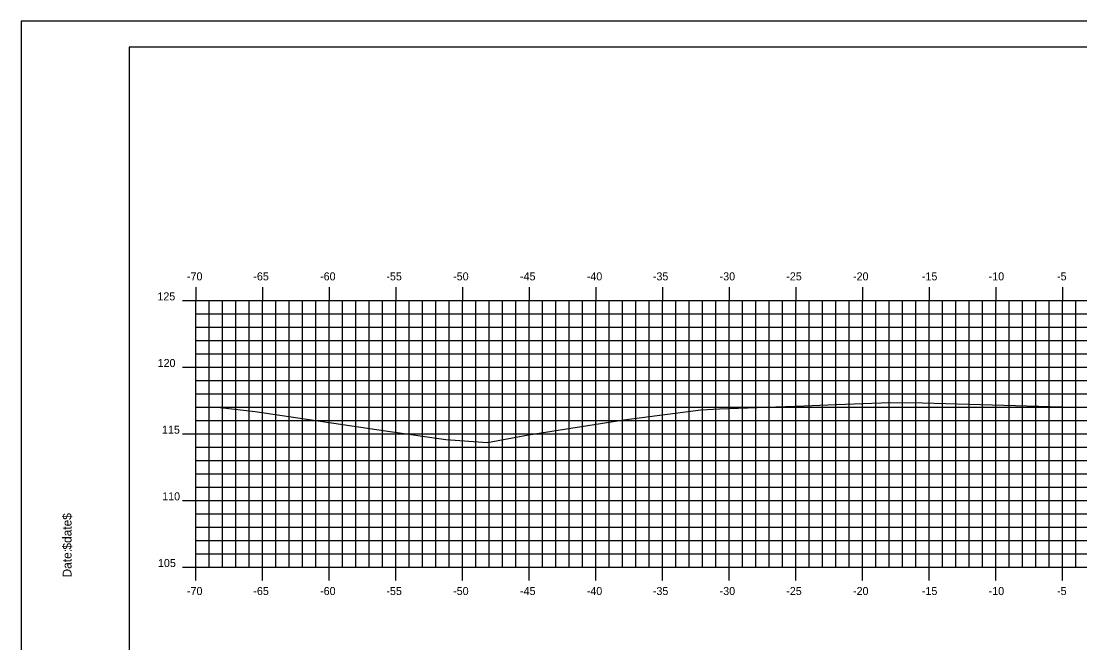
# Model space of a CAD drawing. Extents: x 853734 to 853906, y 365624 to 365734.
# Drawn here: x 853734.2 to 853813.6, y 365687.3 to 365734 of the extents above; entities that cross this region are included whole.
import ezdxf

# ---------------------------------------------------------------- set-up
doc = ezdxf.new("R2010")
doc.units = 0
for name, color, linetype in [('BORDER', 7, 'Continuous'), ('H_V ANNOTATION', 7, 'Continuous'), ('M_Roadway_Centerline', 7, 'Continuous'), ('MAJOR', 7, 'Continuous'), ('MINOR', 7, 'Continuous'), ('PLOT BOUNDARY', 7, 'Continuous'), ('S_Roadway_Centerline', 7, 'Continuous')]:
    doc.layers.add(name, color=color, linetype=linetype)

msp = doc.modelspace()

# ---------------------------------------------------------------- linework, layer by layer
at = {"layer": 'BORDER'}
msp.add_lwpolyline([(853742.331, 365627.027), (853902.331, 365627.027), (853902.331, 365732.027), (853742.331, 365732.027)], close=True, dxfattribs=at)
at = {"layer": 'MAJOR'}
for p, q in [((853747.331, 365714.029), (853747.331, 365713.027)), ((853752.331, 365714.029), (853752.331, 365713.027)), ((853757.331, 365714.029), (853757.331, 365713.027)), ((853762.331, 365714.029), (853762.331, 365713.027)), ((853767.331, 365714.029), (853767.331, 365713.027)), ((853772.331, 365714.029), (853772.331, 365713.027)), ((853777.331, 365714.029), (853777.331, 365713.027)), ((853782.331, 365714.029), (853782.331, 365713.027)), ((853787.331, 365714.029), (853787.331, 365713.027)), ((853792.331, 365714.029), (853792.331, 365713.027)), ((853797.331, 365714.029), (853797.331, 365713.027)), ((853802.331, 365714.029), (853802.331, 365713.027)), ((853807.331, 365714.029), (853807.331, 365713.027)), ((853812.331, 365714.029), (853812.331, 365713.027)), ((853746.329, 365713.027), (853747.331, 365713.027)), ((853747.331, 365713.027), (853887.331, 365713.027)), ((853747.331, 365693.027), (853747.331, 365713.027)), ((853747.331, 365693.027), (853747.331, 365713.027)), ((853747.331, 365713.027), (853887.331, 365713.027)), ((853752.331, 365693.027), (853752.331, 365713.027)), ((853757.331, 365693.027), (853757.331, 365713.027)), ((853762.331, 365693.027), (853762.331, 365713.027)), ((853767.331, 365693.027), (853767.331, 365713.027)), ((853772.331, 365693.027), (853772.331, 365713.027)), ((853777.331, 365693.027), (853777.331, 365713.027)), ((853782.331, 365693.027), (853782.331, 365713.027)), ((853787.331, 365693.027), (853787.331, 365713.027)), ((853792.331, 365693.027), (853792.331, 365713.027)), ((853797.331, 365693.027), (853797.331, 365713.027)), ((853802.331, 365693.027), (853802.331, 365713.027)), ((853807.331, 365693.027), (853807.331, 365713.027)), ((853812.331, 365693.027), (853812.331, 365713.027)), ((853746.329, 365708.027), (853747.331, 365708.027)), ((853747.331, 365708.027), (853887.331, 365708.027)), ((853746.329, 365703.027), (853747.331, 365703.027)), ((853747.331, 365703.027), (853887.331, 365703.027)), ((853746.329, 365698.027), (853747.331, 365698.027)), ((853747.331, 365698.027), (853887.331, 365698.027)), ((853746.329, 365693.027), (853747.331, 365693.027)), ((853747.331, 365693.027), (853887.331, 365693.027)), ((853747.331, 365693.027), (853887.331, 365693.027)), ((853747.331, 365692.025), (853747.331, 365693.027)), ((853752.331, 365692.025), (853752.331, 365693.027)), ((853757.331, 365692.025), (853757.331, 365693.027)), ((853762.331, 365692.025), (853762.331, 365693.027)), ((853767.331, 365692.025), (853767.331, 365693.027)), ((853772.331, 365692.025), (853772.331, 365693.027)), ((853777.331, 365692.025), (853777.331, 365693.027)), ((853782.331, 365692.025), (853782.331, 365693.027)), ((853787.331, 365692.025), (853787.331, 365693.027)), ((853792.331, 365692.025), (853792.331, 365693.027)), ((853797.331, 365692.025), (853797.331, 365693.027)), ((853802.331, 365692.025), (853802.331, 365693.027)), ((853807.331, 365692.025), (853807.331, 365693.027)), ((853812.331, 365692.025), (853812.331, 365693.027))]:
    msp.add_line(p, q, dxfattribs=at)
at = {"layer": 'MINOR'}
for p, q in [((853748.331, 365693.027), (853748.331, 365713.027)), ((853749.331, 365693.027), (853749.331, 365713.027)), ((853750.331, 365693.027), (853750.331, 365713.027)), ((853751.331, 365693.027), (853751.331, 365713.027)), ((853753.331, 365693.027), (853753.331, 365713.027)), ((853754.331, 365693.027), (853754.331, 365713.027)), ((853755.331, 365693.027), (853755.331, 365713.027)), ((853756.331, 365693.027), (853756.331, 365713.027)), ((853758.331, 365693.027), (853758.331, 365713.027)), ((853759.331, 365693.027), (853759.331, 365713.027)), ((853760.331, 365693.027), (853760.331, 365713.027)), ((853761.331, 365693.027), (853761.331, 365713.027)), ((853763.331, 365693.027), (853763.331, 365713.027)), ((853764.331, 365693.027), (853764.331, 365713.027)), ((853765.331, 365693.027), (853765.331, 365713.027)), ((853766.331, 365693.027), (853766.331, 365713.027)), ((853768.331, 365693.027), (853768.331, 365713.027)), ((853769.331, 365693.027), (853769.331, 365713.027)), ((853770.331, 365693.027), (853770.331, 365713.027)), ((853771.331, 365693.027), (853771.331, 365713.027)), ((853773.331, 365693.027), (853773.331, 365713.027)), ((853774.331, 365693.027), (853774.331, 365713.027)), ((853775.331, 365693.027), (853775.331, 365713.027)), ((853776.331, 365693.027), (853776.331, 365713.027)), ((853778.331, 365693.027), (853778.331, 365713.027)), ((853779.331, 365693.027), (853779.331, 365713.027)), ((853780.331, 365693.027), (853780.331, 365713.027)), ((853781.331, 365693.027), (853781.331, 365713.027)), ((853783.331, 365693.027), (853783.331, 365713.027)), ((853784.331, 365693.027), (853784.331, 365713.027)), ((853785.331, 365693.027), (853785.331, 365713.027)), ((853786.331, 365693.027), (853786.331, 365713.027)), ((853788.331, 365693.027), (853788.331, 365713.027)), ((853789.331, 365693.027), (853789.331, 365713.027)), ((853790.331, 365693.027), (853790.331, 365713.027)), ((853791.331, 365693.027), (853791.331, 365713.027)), ((853793.331, 365693.027), (853793.331, 365713.027)), ((853794.331, 365693.027), (853794.331, 365713.027)), ((853795.331, 365693.027), (853795.331, 365713.027)), ((853796.331, 365693.027), (853796.331, 365713.027)), ((853798.331, 365693.027), (853798.331, 365713.027)), ((853799.331, 365693.027), (853799.331, 365713.027)), ((853800.331, 365693.027), (853800.331, 365713.027)), ((853801.331, 365693.027), (853801.331, 365713.027)), ((853803.331, 365693.027), (853803.331, 365713.027)), ((853804.331, 365693.027), (853804.331, 365713.027)), ((853805.331, 365693.027), (853805.331, 365713.027)), ((853806.331, 365693.027), (853806.331, 365713.027)), ((853808.331, 365693.027), (853808.331, 365713.027)), ((853809.331, 365693.027), (853809.331, 365713.027)), ((853810.331, 365693.027), (853810.331, 365713.027)), ((853811.331, 365693.027), (853811.331, 365713.027)), ((853813.331, 365693.027), (853813.331, 365713.027)), ((853747.331, 365712.027), (853887.331, 365712.027)), ((853747.331, 365712.027), (853748.333, 365712.027)), ((853747.331, 365711.027), (853887.331, 365711.027)), ((853747.331, 365711.027), (853748.333, 365711.027)), ((853747.331, 365710.027), (853887.331, 365710.027)), ((853747.331, 365710.027), (853748.333, 365710.027)), ((853747.331, 365709.027), (853887.331, 365709.027)), ((853747.331, 365709.027), (853748.333, 365709.027)), ((853747.331, 365707.027), (853887.331, 365707.027)), ((853747.331, 365707.027), (853748.333, 365707.027)), ((853747.331, 365706.027), (853887.331, 365706.027)), ((853747.331, 365706.027), (853748.333, 365706.027)), ((853747.331, 365705.027), (853887.331, 365705.027)), ((853747.331, 365705.027), (853748.333, 365705.027)), ((853747.331, 365704.027), (853887.331, 365704.027)), ((853747.331, 365704.027), (853748.333, 365704.027)), ((853747.331, 365702.027), (853887.331, 365702.027)), ((853747.331, 365702.027), (853748.333, 365702.027)), ((853747.331, 365701.027), (853887.331, 365701.027)), ((853747.331, 365701.027), (853748.333, 365701.027)), ((853747.331, 365700.027), (853887.331, 365700.027)), ((853747.331, 365700.027), (853748.333, 365700.027)), ((853747.331, 365699.027), (853887.331, 365699.027)), ((853747.331, 365699.027), (853748.333, 365699.027)), ((853747.331, 365697.027), (853887.331, 365697.027)), ((853747.331, 365697.027), (853748.333, 365697.027)), ((853747.331, 365696.027), (853887.331, 365696.027)), ((853747.331, 365696.027), (853748.333, 365696.027)), ((853747.331, 365695.027), (853887.331, 365695.027)), ((853747.331, 365695.027), (853748.333, 365695.027)), ((853747.331, 365694.027), (853887.331, 365694.027)), ((853747.331, 365694.027), (853748.333, 365694.027))]:
    msp.add_line(p, q, dxfattribs=at)
at = {"layer": 'PLOT BOUNDARY'}
msp.add_lwpolyline([(853734.238, 365623.968), (853904.238, 365623.968), (853904.238, 365733.968), (853734.238, 365733.968)], close=True, dxfattribs=at)
at = {"layer": 'S_Roadway_Centerline'}
msp.add_lwpolyline([(853747.331, 365705.041), (853749.151, 365704.997), (853751.776, 365704.687), (853761.571, 365703.248), (853766.078, 365702.598), (853769.212, 365702.355), (853772.273, 365702.953), (853779.437, 365704.064), (853785.216, 365704.826), (853786.597, 365704.903), (853792.948, 365705.121), (853794.723, 365705.19), (853798.035, 365705.318), (853799.439, 365705.364), (853801.833, 365705.334), (853812.276, 365705.044), (853815.177, 365704.969)], dxfattribs=at)

# ---------------------------------------------------------------- texts
at = {"layer": 'BORDER'}
for s, p in [('$date$', (853738.016, 365694.332)), ('Date:', (853738.016, 365692.244))]:
    msp.add_text(s, height=0.6696, rotation=90, dxfattribs=at).set_placement(p)
at = {"layer": 'H_V ANNOTATION'}
for s, p in [('-70', (853746.673, 365714.527)), ('-65', (853751.649, 365714.527)), ('-60', (853756.657, 365714.527)), ('-55', (853761.627, 365714.527)), ('-50', (853766.635, 365714.527)), ('-45', (853771.649, 365714.527)), ('-40', (853776.657, 365714.527)), ('-35', (853781.611, 365714.527)), ('-30', (853786.619, 365714.527)), ('-25', (853791.617, 365714.527)), ('-20', (853796.625, 365714.527)), ('-15', (853801.788, 365714.527)), ('-10', (853806.796, 365714.527)), ('-5', (853811.922, 365714.527)), ('125', (853744.456, 365713.027)), ('120', (853744.472, 365708.027)), ('115', (853744.798, 365703.027)), ('110', (853744.814, 365698.027)), ('105', (853744.498, 365693.027)), ('-70', (853746.673, 365690.927)), ('-65', (853751.649, 365690.927)), ('-60', (853756.657, 365690.927)), ('-55', (853761.627, 365690.927)), ('-50', (853766.635, 365690.927)), ('-45', (853771.649, 365690.927)), ('-40', (853776.657, 365690.927)), ('-35', (853781.611, 365690.927)), ('-30', (853786.619, 365690.927)), ('-25', (853791.617, 365690.927)), ('-20', (853796.625, 365690.927)), ('-15', (853801.788, 365690.927)), ('-10', (853806.796, 365690.927)), ('-5', (853811.922, 365690.927))]:
    msp.add_text(s, height=0.6, dxfattribs=at).set_placement(p)
at = {"layer": 'M_Roadway_Centerline'}
for s, p in [('C', (853798.03, 365705.318)), ('L', (853798.035, 365705.311))]:
    msp.add_text(s, height=0.0146, dxfattribs=at).set_placement(p)
at = {"layer": 'MAJOR'}
msp.add_text('-', height=0.006, dxfattribs=at).set_placement((853747.327, 365693.027))

doc.saveas('drawing.dxf')
